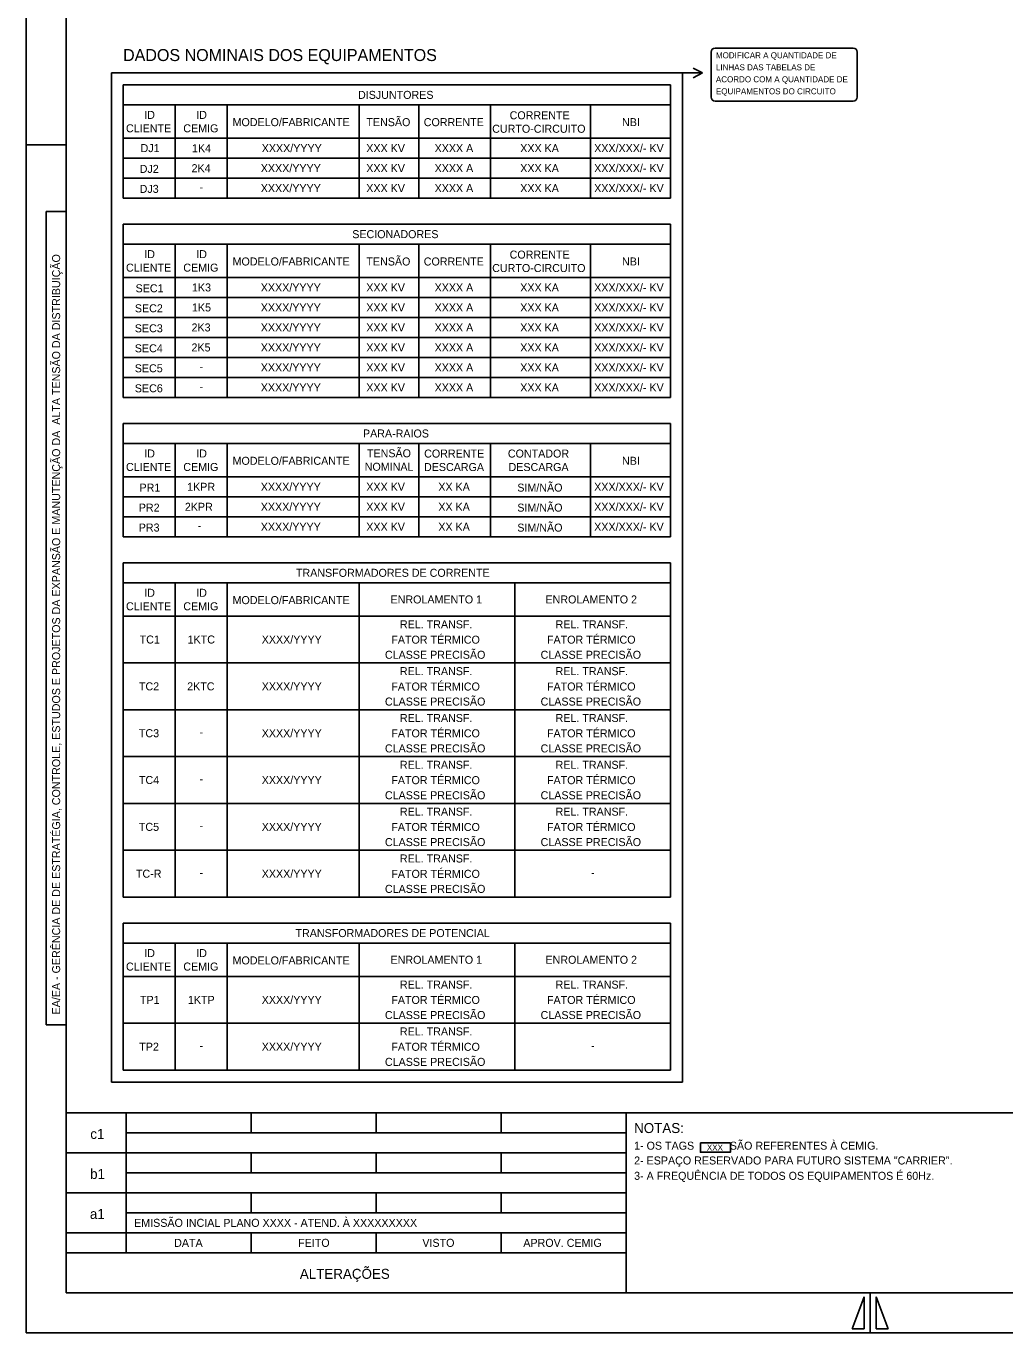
# Model space of a CAD drawing. Extents: x 400 to 1404, y 358 to 952.
# Drawn here: x 562.6 to 807.3, y 358 to 684.6 of the extents above; entities that cross this region are included whole.
import ezdxf

# ---------------------------------------------------------------- set-up
doc = ezdxf.new("R2010")
doc.units = 0
doc.layers.add('New Level (0)', color=7, linetype='Continuous')

# ---------------------------------------------------------------- blocks, each defined once
blk = doc.blocks.new('POINT_DISPLAY')
blk.add_line((0, 0), (0, 0))

msp = doc.modelspace()

# ---------------------------------------------------------------- linework, layer by layer
at = {"layer": 'New Level (0)'}
for p, q in [((562.58, 951.96), (562.58, 357.96)), ((562.58, 951.96), (562.58, 357.96)), ((572.58, 941.96), (572.58, 367.96)), ((572.58, 941.96), (572.58, 367.96)), ((733.84, 666.91), (733.84, 678.16)), ((734.84, 679.16), (742.19, 679.16)), ((742.19, 679.16), (769.38, 679.16)), ((770.38, 678.16), (770.38, 666.91)), ((731.68, 672.95), (729.38, 674.16)), ((583.96, 672.95), (583.96, 420.65)), ((583.96, 672.95), (726.65, 672.95)), ((586.81, 669.95), (586.81, 641.63)), ((586.81, 669.95), (723.65, 669.95)), ((723.65, 669.95), (723.65, 641.63)), ((726.65, 672.95), (726.65, 420.65)), ((726.65, 672.95), (731.68, 672.95)), ((731.68, 672.95), (729.38, 671.75)), ((723.65, 664.95), (586.81, 664.95)), ((599.81, 664.95), (599.81, 641.63)), ((612.81, 641.63), (612.81, 664.95)), ((645.81, 664.95), (645.81, 641.63)), ((660.72, 664.95), (660.72, 641.63)), ((678.66, 664.95), (678.66, 641.63)), ((703.66, 664.95), (703.66, 641.63)), ((769.38, 665.91), (734.84, 665.91)), ((562.58, 654.96), (572.58, 654.96)), ((586.81, 656.63), (723.65, 656.63)), ((586.81, 651.63), (723.65, 651.63)), ((586.81, 646.63), (723.65, 646.63)), ((586.81, 641.63), (723.65, 641.63)), ((567.58, 638.29), (572.58, 638.29)), ((567.58, 434.97), (567.58, 638.29)), ((586.81, 635.13), (586.81, 591.8)), ((586.81, 635.13), (723.65, 635.13)), ((723.65, 635.13), (723.65, 591.8)), ((723.65, 630.13), (586.81, 630.13)), ((599.81, 630.13), (599.81, 591.8)), ((612.81, 591.8), (612.81, 630.13)), ((645.81, 630.13), (645.81, 591.8)), ((660.72, 630.13), (660.72, 591.8)), ((678.66, 630.13), (678.66, 591.8)), ((703.66, 630.13), (703.66, 591.8)), ((586.81, 621.8), (723.65, 621.8)), ((586.81, 616.8), (723.65, 616.8)), ((586.81, 611.8), (723.65, 611.8)), ((586.81, 606.8), (723.65, 606.8)), ((586.81, 601.8), (723.65, 601.8)), ((586.81, 596.8), (723.65, 596.8)), ((586.81, 591.8), (723.65, 591.8)), ((586.81, 585.3), (586.81, 556.97)), ((586.81, 585.3), (723.65, 585.3)), ((723.65, 585.3), (723.65, 556.97)), ((723.65, 580.3), (586.81, 580.3)), ((599.81, 580.3), (599.81, 556.97)), ((612.81, 556.97), (612.81, 580.3)), ((645.81, 580.3), (645.81, 556.97)), ((660.72, 580.3), (660.72, 556.97)), ((678.66, 580.3), (678.66, 556.97)), ((703.66, 580.3), (703.66, 556.97)), ((586.81, 571.97), (723.65, 571.97)), ((629.06, 571.97), (723.65, 571.97)), ((586.81, 566.97), (723.65, 566.97)), ((586.81, 561.97), (723.65, 561.97)), ((586.81, 556.97), (723.65, 556.97)), ((586.81, 550.47), (586.81, 466.9)), ((586.81, 550.47), (723.65, 550.47)), ((723.65, 550.47), (723.65, 466.9)), ((723.65, 545.47), (586.81, 545.47)), ((599.81, 545.47), (599.81, 466.9)), ((612.81, 466.9), (612.81, 545.47)), ((645.81, 545.47), (645.81, 466.9)), ((684.73, 545.47), (684.73, 466.9)), ((586.81, 537.14), (723.65, 537.14)), ((586.81, 525.44), (723.65, 525.44)), ((586.81, 513.73), (723.65, 513.73)), ((586.81, 502.02), (723.65, 502.02)), ((586.81, 490.31), (723.65, 490.31)), ((586.81, 478.6), (723.65, 478.6)), ((586.81, 466.9), (723.65, 466.9)), ((586.81, 460.4), (586.81, 423.65)), ((586.81, 460.4), (723.65, 460.4)), ((723.65, 460.4), (723.65, 423.65)), ((723.65, 455.4), (586.81, 455.4)), ((599.81, 455.4), (599.81, 423.65)), ((612.81, 423.65), (612.81, 455.4)), ((645.81, 455.4), (645.81, 423.65)), ((684.73, 455.4), (684.73, 423.65)), ((586.81, 447.07), (723.65, 447.07)), ((572.58, 434.97), (567.58, 434.97)), ((586.81, 435.36), (723.65, 435.36)), ((586.81, 423.65), (723.65, 423.65)), ((726.65, 420.65), (583.96, 420.65)), ((572.58, 412.96), (1393.58, 412.96)), ((587.58, 377.96), (587.58, 412.96)), ((618.83, 407.96), (618.83, 412.96)), ((650.08, 407.96), (650.08, 412.96)), ((681.33, 407.96), (681.33, 412.96)), ((712.58, 412.96), (712.58, 367.96)), ((587.58, 407.96), (712.58, 407.96)), ((572.58, 402.96), (712.58, 402.96)), ((618.83, 397.96), (618.83, 402.96)), ((650.08, 397.96), (650.08, 402.96)), ((681.33, 397.96), (681.33, 402.96)), ((587.58, 397.96), (712.58, 397.96)), ((572.58, 392.96), (712.58, 392.96)), ((618.83, 387.96), (618.83, 392.96)), ((650.08, 387.96), (650.08, 392.96)), ((681.33, 387.96), (681.33, 392.96)), ((587.58, 387.96), (712.58, 387.96)), ((572.58, 382.96), (712.58, 382.96)), ((618.83, 377.96), (618.83, 382.96)), ((650.08, 377.96), (650.08, 382.96)), ((681.33, 377.96), (681.33, 382.96)), ((572.58, 377.96), (712.58, 377.96)), ((572.58, 367.96), (1393.58, 367.96)), ((572.58, 367.96), (1393.58, 367.96)), ((769.08, 358.96), (772.08, 366.96)), ((772.08, 366.96), (772.08, 358.96)), ((773.58, 367.96), (773.58, 357.96)), ((775.08, 366.96), (775.08, 358.96)), ((778.08, 358.96), (775.08, 366.96)), ((562.58, 357.96), (1403.58, 357.96)), ((562.58, 357.96), (1403.58, 357.96)), ((772.08, 358.96), (769.08, 358.96)), ((775.08, 358.96), (778.08, 358.96))]:
    msp.add_line(p, q, dxfattribs=at)
msp.add_lwpolyline([(731.16, 405.44), (738.67, 405.44), (738.67, 403.1), (731.16, 403.1)], close=True, dxfattribs=at)
for centre, start, end in [((734.84, 678.16), 90, 180), ((769.38, 678.16), 0, 90), ((734.84, 666.91), 180, 270), ((769.38, 666.91), 270, 0)]:
    msp.add_arc(centre, 1, start, end, dxfattribs=at)

# ---------------------------------------------------------------- block references
for p in [(655.23, 656.63), (655.23, 537.14), (655.23, 447.07)]:
    msp.add_blockref('POINT_DISPLAY', p, dxfattribs=at)

# ---------------------------------------------------------------- texts
for s, height, p in [('DADOS NOMINAIS DOS EQUIPAMENTOS', 3, (586.81, 675.91)), ('MODIFICAR A QUANTIDADE DE ', 1.5, (735.03, 676.6)), ('LINHAS DAS TABELAS DE ', 1.5, (735.03, 673.6)), ('ACORDO COM A QUANTIDADE DE ', 1.5, (735.03, 670.6)), ('DISJUNTORES', 2, (645.55, 666.45)), ('EQUIPAMENTOS DO CIRCUITO', 1.5, (735.03, 667.6)), ('ID', 2, (592.1, 661.45)), ('ID', 2, (605.1, 661.45)), ('CORRENTE', 2, (683.46, 661.35)), ('CLIENTE', 2, (587.54, 658.09)), ('CEMIG', 2, (601.87, 658.09)), ('MODELO/FABRICANTE', 2, (614.19, 659.63)), ('TENSÃO', 2, (647.65, 659.63)), ('CORRENTE', 2, (661.99, 659.63)), ('CURTO-CIRCUITO', 2, (679.1, 657.98)), ('NBI', 2, (711.56, 659.63)), ('DJ1', 2, (591.19, 653.14)), ('1K4', 2, (604.05, 653.12)), ('XXXX/YYYY', 2, (621.48, 653.13)), ('XXX KV', 2, (647.62, 653.13)), ('XXXX A', 2, (664.7, 653.13)), ('XXX KA', 2, (686.11, 653.13)), ('XXX/XXX/- KV', 2, (704.59, 653.13)), ('2K4', 2, (603.94, 648.12)), ('XXXX/YYYY', 2, (621.24, 648.13)), ('XXX KV', 2, (647.62, 648.13)), ('XXXX A', 2, (664.7, 648.13)), ('XXX KA', 2, (686.11, 648.13)), ('XXX/XXX/- KV', 2, (704.59, 648.13)), ('DJ2', 2, (590.97, 647.95)), ('DJ3', 2, (590.96, 642.95)), ('-', 2, (605.94, 643.4)), ('XXXX/YYYY', 2, (621.24, 643.13)), ('XXX KV', 2, (647.62, 643.13)), ('XXXX A', 2, (664.7, 643.13)), ('XXX KA', 2, (686.11, 643.13)), ('XXX/XXX/- KV', 2, (704.59, 643.13)), ('SECIONADORES', 2, (644.11, 631.63)), ('ID', 2, (592.1, 626.63)), ('ID', 2, (605.1, 626.63)), ('TENSÃO', 2, (647.65, 624.8)), ('CORRENTE', 2, (683.46, 626.52)), ('CLIENTE', 2, (587.54, 623.26)), ('CEMIG', 2, (601.87, 623.26)), ('MODELO/FABRICANTE', 2, (614.19, 624.8)), ('CORRENTE', 2, (661.99, 624.8)), ('CURTO-CIRCUITO', 2, (679.1, 623.16)), ('NBI', 2, (711.56, 624.8)), ('SEC1', 2, (589.94, 618.1)), ('1K3', 2, (604.04, 618.31)), ('XXXX/YYYY', 2, (621.24, 618.3)), ('XXX KV', 2, (647.62, 618.3)), ('XXXX A', 2, (664.7, 618.3)), ('XXX KA', 2, (686.11, 618.3)), ('XXX/XXX/- KV', 2, (704.59, 618.3)), ('SEC2', 2, (589.76, 613.1)), ('1K5', 2, (604.04, 613.31)), ('XXXX/YYYY', 2, (621.24, 613.3)), ('XXX KV', 2, (647.62, 613.3)), ('XXXX A', 2, (664.7, 613.3)), ('XXX KA', 2, (686.11, 613.3)), ('XXX/XXX/- KV', 2, (704.59, 613.3)), ('SEC3', 2, (589.75, 608.1)), ('2K3', 2, (603.93, 608.31)), ('XXXX/YYYY', 2, (621.24, 608.3)), ('XXX KV', 2, (647.62, 608.3)), ('XXXX A', 2, (664.7, 608.3)), ('XXX KA', 2, (686.11, 608.3)), ('XXX/XXX/- KV', 2, (704.59, 608.3)), ('SEC4', 2, (589.75, 603.1)), ('2K5', 2, (603.92, 603.31)), ('XXXX/YYYY', 2, (621.24, 603.3)), ('XXX KV', 2, (647.62, 603.3)), ('XXXX A', 2, (664.7, 603.3)), ('XXX KA', 2, (686.11, 603.3)), ('XXX/XXX/- KV', 2, (704.59, 603.3)), ('SEC5', 2, (589.74, 598.1)), ('-', 2, (605.94, 598.57)), ('XXXX/YYYY', 2, (621.24, 598.3)), ('XXX KV', 2, (647.62, 598.3)), ('XXXX A', 2, (664.7, 598.3)), ('XXX KA', 2, (686.11, 598.3)), ('XXX/XXX/- KV', 2, (704.59, 598.3)), ('SEC6', 2, (589.75, 593.1)), ('XXXX/YYYY', 2, (621.24, 593.3)), ('XXX KV', 2, (647.62, 593.3)), ('XXXX A', 2, (664.7, 593.3)), ('XXX KA', 2, (686.11, 593.3)), ('XXX/XXX/- KV', 2, (704.59, 593.3)), ('-', 2, (605.94, 593.57)), ('PARA-RAIOS', 2, (646.79, 581.8)), ('ID', 2, (592.1, 576.8)), ('ID', 2, (605.1, 576.8)), ('TENSÃO ', 2, (647.79, 576.85)), ('CORRENTE', 2, (662.09, 576.78)), ('CONTADOR', 2, (683.02, 576.78)), ('CLIENTE', 2, (587.54, 573.43)), ('CEMIG', 2, (601.87, 573.43)), ('MODELO/FABRICANTE', 2, (614.19, 574.97)), ('NOMINAL', 2, (647.23, 573.48)), ('DESCARGA', 2, (662.05, 573.41)), ('DESCARGA', 2, (683.19, 573.41)), ('NBI', 2, (711.56, 574.97)), ('PR1', 2, (590.92, 568.27)), ('1KPR', 2, (602.83, 568.47)), ('XXXX/YYYY', 2, (621.24, 568.47)), ('XXX KV', 2, (647.62, 568.47)), ('XX KA', 2, (665.63, 568.47)), ('SIM/NÃO', 2, (685.38, 568.27)), ('XXX/XXX/- KV', 2, (704.59, 568.47)), ('PR2', 2, (590.74, 563.27)), ('2KPR', 2, (602.26, 563.47)), ('XXXX/YYYY', 2, (621.24, 563.47)), ('XXX KV', 2, (647.62, 563.47)), ('XX KA', 2, (665.63, 563.47)), ('SIM/NÃO', 2, (685.38, 563.27)), ('XXX/XXX/- KV', 2, (704.59, 563.47)), ('PR3', 2, (590.73, 558.29)), ('-', 2, (605.47, 558.75)), ('XXXX/YYYY', 2, (621.24, 558.47)), ('XXX KV', 2, (647.62, 558.47)), ('XX KA', 2, (665.63, 558.47)), ('SIM/NÃO', 2, (685.38, 558.27)), ('XXX/XXX/- KV', 2, (704.59, 558.47)), ('TRANSFORMADORES DE CORRENTE', 2, (630.03, 546.97)), ('ID', 2, (592.1, 541.97)), ('ID', 2, (605.1, 541.97)), ('ENROLAMENTO 1', 2, (653.68, 540.31)), ('ENROLAMENTO 2', 2, (692.42, 540.31)), ('CLIENTE', 2, (587.54, 538.6)), ('CEMIG', 2, (601.87, 538.6)), ('MODELO/FABRICANTE', 2, (614.19, 540.14)), ('REL. TRANSF.', 2, (656.03, 534.09)), ('REL. TRANSF.', 2, (694.95, 534.09)), ('FATOR TÉRMICO', 2, (653.88, 530.25)), ('FATOR TÉRMICO', 2, (692.8, 530.25)), ('TC1', 2, (590.96, 530.29)), ('1KTC', 2, (602.95, 530.29)), ('XXXX/YYYY', 2, (621.48, 530.29)), ('CLASSE PRECISÃO', 2, (652.28, 526.48)), ('CLASSE PRECISÃO', 2, (691.2, 526.48)), ('REL. TRANSF.', 2, (656.03, 522.38)), ('REL. TRANSF.', 2, (694.95, 522.38)), ('TC2', 2, (590.78, 518.58)), ('2KTC', 2, (602.84, 518.58)), ('XXXX/YYYY', 2, (621.48, 518.58)), ('FATOR TÉRMICO', 2, (653.88, 518.54)), ('FATOR TÉRMICO', 2, (692.8, 518.54)), ('CLASSE PRECISÃO', 2, (652.28, 514.78)), ('CLASSE PRECISÃO', 2, (691.2, 514.78)), ('REL. TRANSF.', 2, (656.03, 510.68)), ('REL. TRANSF.', 2, (694.95, 510.68)), ('TC3', 2, (590.77, 506.87)), ('-', 2, (605.94, 507.15)), ('XXXX/YYYY', 2, (621.48, 506.87)), ('FATOR TÉRMICO', 2, (653.88, 506.84)), ('FATOR TÉRMICO', 2, (692.8, 506.84)), ('CLASSE PRECISÃO', 2, (652.28, 503.07)), ('CLASSE PRECISÃO', 2, (691.2, 503.07)), ('REL. TRANSF.', 2, (656.03, 498.97)), ('REL. TRANSF.', 2, (694.95, 498.97)), ('TC4', 2, (590.78, 495.17)), ('XXXX/YYYY', 2, (621.48, 495.17)), ('FATOR TÉRMICO', 2, (653.88, 495.13)), ('FATOR TÉRMICO', 2, (692.8, 495.13)), ('-', 2, (605.94, 495.44)), ('CLASSE PRECISÃO', 2, (652.28, 491.36)), ('CLASSE PRECISÃO', 2, (691.2, 491.36)), ('REL. TRANSF.', 2, (656.03, 487.26)), ('REL. TRANSF.', 2, (694.95, 487.26)), ('TC5', 2, (590.76, 483.46)), ('-', 2, (605.94, 483.73)), ('XXXX/YYYY', 2, (621.48, 483.46)), ('FATOR TÉRMICO', 2, (653.88, 483.42)), ('FATOR TÉRMICO', 2, (692.8, 483.42)), ('CLASSE PRECISÃO', 2, (652.28, 479.65)), ('CLASSE PRECISÃO', 2, (691.2, 479.65)), ('REL. TRANSF.', 2, (656.03, 475.55)), ('TC-R', 2, (590.03, 471.75)), ('XXXX/YYYY', 2, (621.48, 471.75)), ('FATOR TÉRMICO', 2, (653.88, 471.71)), ('-', 2, (605.94, 472.03)), ('CLASSE PRECISÃO', 2, (652.28, 467.95)), ('-', 2, (703.81, 472.03)), ('TRANSFORMADORES DE POTENCIAL', 2, (629.92, 456.9)), ('ID', 2, (592.1, 451.9)), ('ID', 2, (605.1, 451.9)), ('MODELO/FABRICANTE', 2, (614.19, 450.07)), ('ENROLAMENTO 1', 2, (653.68, 450.23)), ('ENROLAMENTO 2', 2, (692.42, 450.23)), ('CLIENTE', 2, (587.54, 448.53)), ('CEMIG', 2, (601.87, 448.53)), ('REL. TRANSF.', 2, (656.03, 444.02)), ('REL. TRANSF.', 2, (694.95, 444.02)), ('TP1', 2, (591.04, 440.21)), ('1KTP', 2, (603.03, 440.21)), ('XXXX/YYYY', 2, (621.48, 440.21)), ('FATOR TÉRMICO', 2, (653.88, 440.18)), ('FATOR TÉRMICO', 2, (692.8, 440.18)), ('CLASSE PRECISÃO', 2, (652.28, 436.41)), ('CLASSE PRECISÃO', 2, (691.2, 436.41)), ('REL. TRANSF.', 2, (656.03, 432.31)), ('TP2', 2, (590.86, 428.5)), ('-', 2, (605.94, 428.78)), ('XXXX/YYYY', 2, (621.48, 428.51)), ('FATOR TÉRMICO', 2, (653.88, 428.47)), ('-', 2, (703.81, 428.78)), ('CLASSE PRECISÃO', 2, (652.28, 424.7)), ('XXX', 1.5, (732.77, 403.54))]:
    msp.add_text(s, height=height).set_placement(p)
msp.add_text('EA/EA - GERÊNCIA DE DE ESTRATÉGIA, CONTROLE, ESTUDOS E PROJETOS DA EXPANSÃO E MANUTENÇÃO DA  ALTA TENSÃO DA DISTRIBUIÇÃO', height=2, rotation=90, dxfattribs=at).set_placement((571.08, 437.56))
for s, height, p in [('c1', 2.5, (578.62, 406.44)), ('NOTAS:', 2.5, (714.58, 407.91)), ('1- OS TAGS            SÃO REFERENTES À CEMIG.', 2, (714.58, 403.75)), ('2- ESPAÇO RESERVADO PARA FUTURO SISTEMA "CARRIER".', 2, (714.58, 400.05)), ('b1', 2.5, (578.57, 396.44)), ('3- A FREQUÊNCIA DE TODOS OS EQUIPAMENTOS É 60Hz.', 2, (714.58, 396.22)), ('a1', 2.5, (578.52, 386.44)), ('EMISSÃO INCIAL PLANO XXXX - ATEND. À XXXXXXXXX', 2, (589.58, 384.46)), ('DATA', 2, (599.58, 379.46)), ('FEITO', 2, (630.58, 379.46)), ('VISTO', 2, (661.64, 379.46)), ('APROV. CEMIG', 2, (686.88, 379.46)), ('ALTERAÇÕES', 2.5, (631.01, 371.46))]:
    msp.add_text(s, height=height, dxfattribs=at).set_placement(p)

doc.saveas('drawing.dxf')
